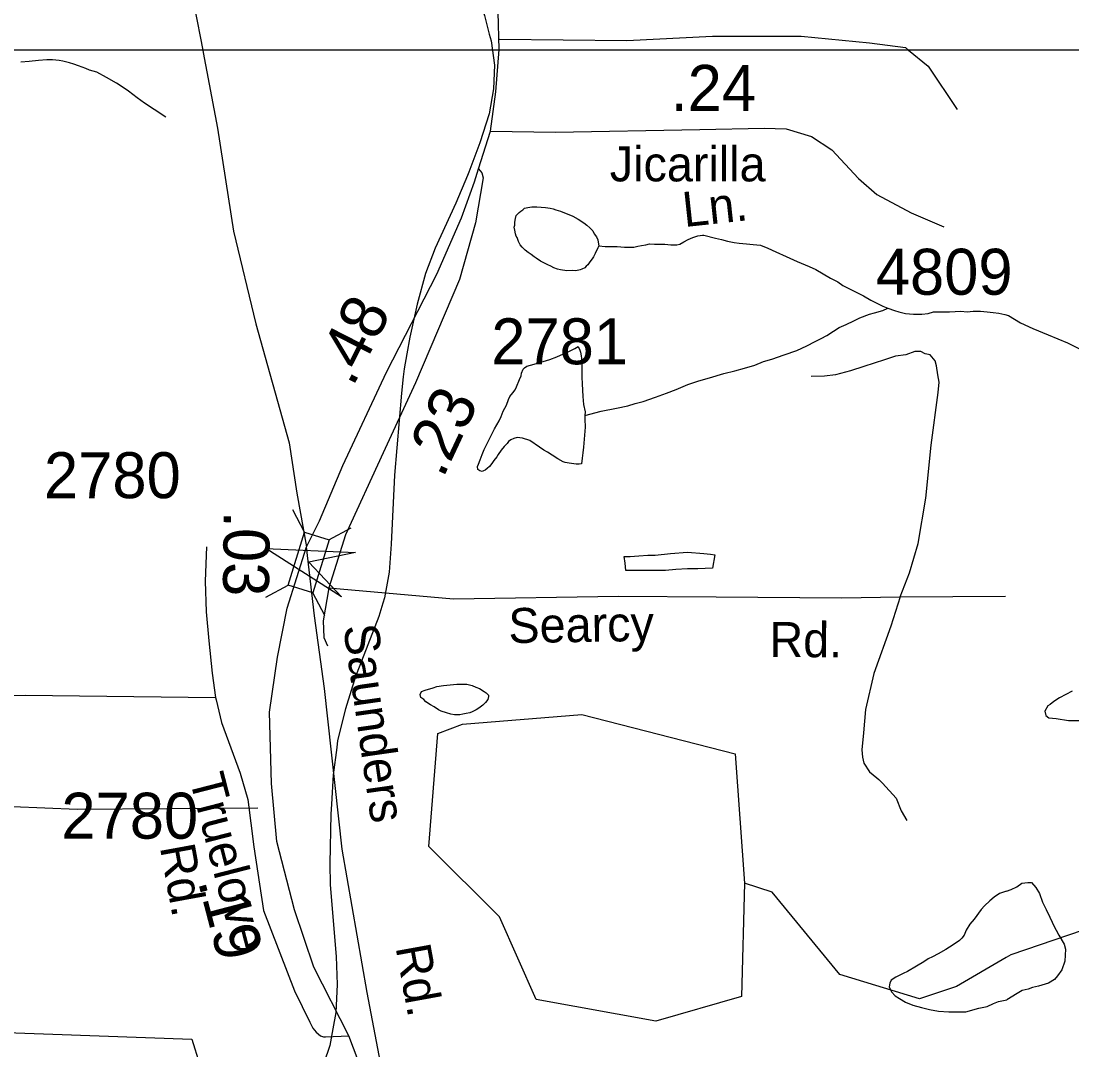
# Model space of a CAD drawing. Extents: x 2001466 to 2224147, y 644118 to 847247.
# Drawn here: x 2071761 to 2074618, y 655454 to 658253 of the extents above; entities that cross this region are included whole.
import ezdxf

# ---------------------------------------------------------------- set-up
doc = ezdxf.new("R2010")
doc.units = 0
for name, color, linetype in [('Exist Boundary Political City Limit New', 7, 'Continuous'), ('Exist Hydrographic Misc Water Feature', 7, 'Continuous'), ('Exist Railroad Mainline', 7, 'Continuous'), ('Exist Road Non-System Type 51', 7, 'Continuous'), ('Exist Road Non-System Type 51 Label', 7, 'Continuous'), ('Exist Road Primary NC Attributed', 7, 'Continuous'), ('Exist Road Primary NC Service Mileage Hundredths English Label', 7, 'Continuous'), ('Exist Road Primary NC Structure Standard Bridge CELL', 7, 'Continuous'), ('Exist Road Secondary Mileage Hundredths English Label', 7, 'Continuous'), ('Exist Road Secondary Structure Standard Bridge Attributed CELL', 7, 'Continuous'), ('Exist Road Secondary Type 51 Attributed', 7, 'Continuous'), ('Exist Road Secondary Type 51 Label', 7, 'Continuous'), ('Exist Road Secondary Type 51 Number Label', 7, 'Continuous'), ('Map Preparation Boundary City Limit Buffer Line', 7, 'Continuous'), ('Map Preparation Inset Cut Line', 7, 'Continuous')]:
    doc.layers.add(name, color=color, linetype=linetype)

msp = doc.modelspace()

# ---------------------------------------------------------------- linework, layer by layer
at = {"layer": 'Exist Boundary Political City Limit New'}
msp.add_lwpolyline([(2070007.4, 655563.6), (2072225.1, 655483.6), (2072246.1, 655416.9), (2072265, 655359.6), (2072449.4, 655349.1), (2072634.1, 655340.1), (2072657.8, 655272), (2072670, 655228.4), (2072685.6, 655160.9), (2072704.4, 655074.9), (2072724.5, 655000)], dxfattribs=at)
at = {"layer": 'Exist Hydrographic Misc Water Feature'}
for p, q in [((2072978.1, 657841.3), (2072974.9, 657832.8)), ((2072674.3, 656479.2), (2072670.8, 656469.9)), ((2072600.8, 655961.3), (2072601.9, 655903.3)), ((2074451.8, 655713), (2074439.1, 655705.7))]:
    msp.add_line(p, q, dxfattribs=at)
for points in [[(2073007, 658307.3), (2073020.8, 658267.5), (2073034.1, 658216.6)], [(2073007, 658307.3), (2073020.8, 658267.5), (2073034.1, 658216.6)], [(2073034.1, 658216.6), (2073038.8, 658198.8), (2073047.9, 658133.1)], [(2073034.1, 658216.6), (2073038.8, 658198.8), (2073047.9, 658133.1)], [(2072155.1, 657991.7), (2072123.1, 658011.7), (2072097, 658029.6), (2072076.9, 658043.6), (2072052.9, 658061.6), (2072033.1, 658075.5), (2072021, 658083.5), (2071993.1, 658099.4), (2071966.8, 658113.3), (2071946.9, 658119.3), (2071936.9, 658123.3), (2071917, 658131.2), (2071904.9, 658135.2), (2071892.8, 658139.2), (2071875, 658143.2), (2071864.9, 658145.2), (2071846.9, 658147.1), (2071830.9, 658147.1), (2071808.9, 658145.1), (2071782.9, 658143), (2071760.9, 658141)], [(2073047.9, 658133.1), (2073045.6, 658068.8), (2073033.7, 658000), (2073008.7, 657921.1), (2072978.1, 657841.3)], [(2073047.9, 658133.1), (2073045.6, 658068.8), (2073033.7, 658000), (2073008.7, 657921.1), (2072978.1, 657841.3)], [(2072974.9, 657832.8), (2072942.9, 657757.5), (2072886.7, 657635), (2072860.8, 657566), (2072837.9, 657482.6)], [(2072974.9, 657832.8), (2072942.9, 657757.5), (2072886.7, 657635), (2072860.8, 657566), (2072837.9, 657482.6)], [(2073331.6, 657641.8), (2073329.4, 657636.1), (2073321.6, 657620.2), (2073317.7, 657611.9), (2073313.6, 657606), (2073307.7, 657598), (2073301.7, 657589.9), (2073297.6, 657586.1), (2073293.5, 657581.9), (2073285.5, 657577.8), (2073281.4, 657576), (2073269.7, 657573.7), (2073259.9, 657574), (2073245.3, 657573.7), (2073227.5, 657576), (2073219.7, 657577.6), (2073209.8, 657582), (2073201.4, 657585.7), (2073193.6, 657589.7), (2073185.9, 657593.7), (2073173.6, 657599.6), (2073161.9, 657607.5), (2073155.7, 657611.7), (2073147.7, 657617.7), (2073139.7, 657623.4), (2073131.9, 657629.5), (2073123.5, 657637.7), (2073117.6, 657643.8), (2073113.3, 657653.4), (2073109.6, 657663.7), (2073107.5, 657667.6), (2073105.7, 657673.6), (2073103.4, 657683.6), (2073101.4, 657691.7), (2073103.2, 657697.5), (2073103.2, 657705.6), (2073105.5, 657715.4), (2073107.1, 657723.7), (2073111.2, 657727.5), (2073115.3, 657731.8), (2073119.4, 657735.6), (2073125.6, 657739.5), (2073129.7, 657743.8), (2073139.3, 657745.6), (2073149.4, 657747.7), (2073157.6, 657747.7), (2073163.5, 657747.6), (2073187.3, 657745.6), (2073199.4, 657743.8), (2073207.6, 657741.7), (2073215.2, 657739.7), (2073221.3, 657737.6), (2073227.3, 657735.9), (2073261.1, 657721.8), (2073275.7, 657713.9), (2073291.3, 657703.9), (2073299.2, 657697.8), (2073307.2, 657690.1), (2073315.2, 657682), (2073319.5, 657674.1), (2073325.3, 657665.9), (2073329.6, 657657.9), (2073331.4, 657645.9), (2073331.6, 657641.8)], [(2073331.6, 657641.8), (2073349.5, 657639.9), (2073365.3, 657639.9), (2073381.5, 657639.9), (2073401.6, 657638.1), (2073415.5, 657638), (2073427.4, 657638.2), (2073437.7, 657640.3), (2073447.7, 657642.1), (2073459.4, 657644.3), (2073469.6, 657646.4), (2073483.6, 657646.3), (2073497.7, 657646.2), (2073511.7, 657646.2), (2073527.5, 657644.5), (2073543.7, 657644.5), (2073551.7, 657646.2), (2073563.4, 657652.5), (2073575.2, 657658.4), (2073587.3, 657664.3), (2073595.3, 657666.7), (2073601.3, 657668.7), (2073613.4, 657670.5), (2073617.3, 657670.7)], [(2073617.3, 657670.7), (2073649.1, 657662.6), (2073665.1, 657658.6), (2073681.5, 657654.5), (2073699.5, 657650.5), (2073713.7, 657648.8), (2073733.1, 657646.6), (2073751.6, 657644.7), (2073771.3, 657642.9), (2073791.2, 657635), (2073813.3, 657624.8), (2073841.4, 657612.8), (2073871.5, 657598.9), (2073903.5, 657585.1), (2073921.4, 657577.2), (2073941.5, 657565.2), (2073961.6, 657553.2), (2073981.7, 657543.3), (2073995.2, 657533.1), (2074011.4, 657525.4), (2074031.9, 657515.4), (2074051.4, 657505.6), (2074071.5, 657493.6), (2074087.7, 657485.5), (2074103.7, 657477.4), (2074117.6, 657471.6)], [(2072837.9, 657482.6), (2072817.8, 657393.2), (2072809.8, 657347.9)], [(2072837.9, 657482.6), (2072817.8, 657393.2), (2072809.8, 657347.9)], [(2073294.1, 657180.2), (2073338.2, 657192.2), (2073380.2, 657200), (2073410.4, 657206.4), (2073430.5, 657212.3), (2073452.2, 657218.3), (2073486.1, 657230.2), (2073516.2, 657240.3), (2073542.2, 657250.5), (2073573.8, 657264.4), (2073604, 657274.4), (2073632.3, 657282.7), (2073672, 657294.6), (2073702, 657301), (2073727.8, 657308.8), (2073755.9, 657316.7), (2073779.7, 657326.9), (2073802, 657332.8), (2073835.9, 657345.2), (2073869.9, 657357), (2073897.8, 657369), (2073919.7, 657381.1), (2073935.9, 657389.2), (2073951.7, 657397.3), (2073970, 657409.2), (2073985.6, 657419.4), (2074004, 657427.2), (2074025.5, 657437.3), (2074041.7, 657445.4), (2074067.6, 657455.2), (2074081.5, 657459.6), (2074103.9, 657465.6), (2074117.6, 657471.6)], [(2074117.6, 657471.6), (2074135.7, 657465.6), (2074147.3, 657461.8), (2074165.4, 657457.8), (2074187.5, 657455.7), (2074209.7, 657455.6), (2074227.5, 657457.8), (2074241.7, 657461.7), (2074263.4, 657461.7), (2074285.5, 657461.9), (2074315.7, 657463.9), (2074333.5, 657462), (2074349.7, 657464), (2074369.6, 657463.8), (2074387.7, 657461.9), (2074403.9, 657459.8), (2074419.7, 657458.2), (2074435.6, 657454.2)], [(2074435.6, 657454.2), (2074445.9, 657452.2), (2074477.9, 657432.4), (2074511.7, 657416.7), (2074553.6, 657399), (2074605.6, 657377.8), (2074649.7, 657356.1), (2074691.8, 657346), (2074747.5, 657334.3), (2074799.6, 657330.5), (2074841.7, 657334.7), (2074877.3, 657350.7), (2074905.4, 657372.9), (2074933.1, 657397.1), (2074961, 657411.1), (2074981.1, 657417.4), (2074997.1, 657421)], [(2073294.1, 657180.2), (2073294.1, 657170.1), (2073294.3, 657148.1), (2073292.3, 657116), (2073290.4, 657094), (2073288.2, 657078.1), (2073286.7, 657064.1), (2073284.9, 657048.2), (2073278.5, 657048), (2073270.3, 657048), (2073250.9, 657050.1), (2073240.4, 657052.1), (2073234.9, 657053.8), (2073220.5, 657062), (2073204.7, 657071.7), (2073192.4, 657080.1), (2073182.8, 657086), (2073170.5, 657093.9), (2073144.6, 657111.6), (2073124.3, 657118), (2073110.2, 657119.7), (2073100.6, 657117.5), (2073092.8, 657113.9), (2073086.4, 657109.5), (2073082.5, 657103.6), (2073074.3, 657095.5), (2073066.7, 657085.7), (2073058.3, 657073.6), (2073054.8, 657067.7), (2073046.6, 657057.5), (2073040.7, 657049.5), (2073034.7, 657041.5), (2073028.6, 657035.5), (2073022.8, 657031.5), (2073018.7, 657029.7), (2073014.4, 657027.5), (2073008.5, 657029.7), (2073002.7, 657033.4), (2073002.3, 657041.5), (2073004.8, 657047.7), (2073008.9, 657059.6), (2073014.6, 657073.8), (2073020.6, 657087.5), (2073038.6, 657123.6), (2073048.3, 657143.7), (2073060.6, 657165.7), (2073066.3, 657177.5), (2073072.1, 657191.6), (2073080.7, 657207.7), (2073086.2, 657223.5), (2073090.3, 657231.8), (2073098.3, 657241.5), (2073104.2, 657249.6), (2073108.1, 657257.5), (2073116.1, 657277.8), (2073120.4, 657287.7), (2073122.1, 657295.5), (2073126.4, 657305.8), (2073130.1, 657309.7), (2073136.2, 657313.7), (2073156.3, 657319.6), (2073198.4, 657331.9), (2073217.8, 657339.8), (2073235.9, 657348.1), (2073250, 657354), (2073266.2, 657362.1), (2073276.1, 657367.9), (2073280, 657358), (2073282, 657352), (2073284.1, 657342), (2073286.1, 657327.9), (2073286.1, 657310), (2073286.1, 657295.8), (2073285.9, 657284.1), (2073286.3, 657266.2), (2073288.4, 657231.8), (2073290.2, 657210), (2073294.5, 657189.9), (2073294.1, 657180.2)], [(2072809.8, 657347.9), (2072802.8, 657307.3), (2072800.2, 657284.9)], [(2072809.8, 657347.9), (2072802.8, 657307.3), (2072800.2, 657284.9)], [(2072800.2, 657284.9), (2072795, 657240.5), (2072776.8, 657017.5), (2072766.9, 656830.5), (2072762, 656754.3), (2072748.9, 656683.8), (2072744.6, 656669.5)], [(2072800.2, 657284.9), (2072795, 657240.5), (2072776.8, 657017.5), (2072766.9, 656830.5), (2072762, 656754.3), (2072748.9, 656683.8), (2072744.6, 656669.5)], [(2073527.1, 656804.7), (2073573.2, 656808.6), (2073617.1, 656804.8), (2073635.1, 656802.9), (2073647, 656800.7), (2073641.1, 656764.7), (2073601.1, 656762.6), (2073573.2, 656762.8), (2073540.8, 656760.8), (2073512.9, 656758.5), (2073472.9, 656758.5), (2073457.1, 656758.4), (2073441.1, 656758.5), (2073417.2, 656758.4), (2073409.2, 656758.4), (2073404.9, 656758.3), (2073403.2, 656778.4), (2073401, 656796.2), (2073416.7, 656796.2), (2073440.9, 656798.2), (2073464.9, 656800.3), (2073485, 656800.5), (2073527.1, 656804.7)], [(2072744.6, 656669.5), (2072733.7, 656633.7), (2072674.3, 656479.2)], [(2072744.6, 656669.5), (2072733.7, 656633.7), (2072674.3, 656479.2)], [(2072670.8, 656469.9), (2072643.1, 656382.6), (2072621.8, 656296), (2072619.3, 656277.3)], [(2072670.8, 656469.9), (2072643.1, 656382.6), (2072621.8, 656296), (2072619.3, 656277.3)], [(2072959.9, 656449.7), (2072973.4, 656449.7), (2072987.6, 656445.5), (2072997.6, 656441.6), (2073007.7, 656437.6), (2073019.8, 656429.7), (2073025.9, 656425.5), (2073031.9, 656419.8), (2073032.1, 656415.7), (2073029.8, 656407.5), (2073023.9, 656399.9), (2073016.1, 656391.8), (2073005.8, 656383.6), (2072998, 656379.9), (2072988, 656373.7), (2072981.6, 656371.8), (2072971.6, 656369.7), (2072961.9, 656367.5), (2072953.9, 656365.5), (2072939.8, 656365.6), (2072930, 656367.5), (2072917.9, 656371.7), (2072903.7, 656375.5), (2072895.9, 656379.5), (2072884, 656387.4), (2072874, 656393.4), (2072861.7, 656401.3), (2072855.9, 656407.5), (2072847.9, 656413.5), (2072845.9, 656421.6), (2072849.8, 656429.5), (2072859.8, 656433.3), (2072881.6, 656439.3), (2072891.6, 656443.4), (2072909.9, 656445.5), (2072927.5, 656447.3), (2072945.7, 656449.4), (2072959.9, 656449.7)], [(2074618.6, 656430.4), (2074584.5, 656412), (2074568.5, 656402.3), (2074558.5, 656394.1), (2074552.3, 656390.1), (2074544.5, 656375.9), (2074546.8, 656364.2), (2074554.8, 656358.1), (2074574.9, 656356.3), (2074608.7, 656350.3), (2074642.8, 656350.5)], [(2073727.8, 655908.1), (2073719.8, 655599.9), (2073486.9, 655532.4), (2073161.9, 655591.5), (2073061.8, 655816.7), (2072869.9, 656007.6), (2072893.9, 656315.4), (2072960.9, 656340.4), (2073285.9, 656366.6), (2073702.8, 656259.7), (2073727.8, 655908.1)], [(2072619.3, 656277.3), (2072609.7, 656202.7), (2072604.7, 656122.8)], [(2072619.3, 656277.3), (2072609.7, 656202.7), (2072604.7, 656122.8)], [(2072604.7, 656122.8), (2072602.9, 656096.2), (2072600.8, 655961.3)], [(2072604.7, 656122.8), (2072602.9, 656096.2), (2072600.8, 655961.3)], [(2072601.9, 655903.3), (2072617.9, 655708.9), (2072620.7, 655632.2)], [(2072601.9, 655903.3), (2072617.9, 655708.9), (2072620.7, 655632.2)], [(2074439.1, 655705.7), (2074303.8, 655627.4), (2074203.7, 655593.3), (2073986.8, 655660.1), (2073802.9, 655883.6), (2073727.8, 655908.1)], [(2074440.4, 655886.3), (2074452.5, 655890.6), (2074468.3, 655898.3), (2074482.2, 655908.4), (2074498.2, 655910), (2074508, 655910.1), (2074520.1, 655896.1), (2074529.8, 655880.1), (2074538.2, 655856.1), (2074548, 655836.3), (2074558.3, 655816.1), (2074564, 655802.3)], [(2074440.4, 655886.3), (2074420.7, 655880.4), (2074406.7, 655870.3), (2074394.8, 655860.4), (2074380.5, 655846.3), (2074370.9, 655836.4), (2074352.4, 655810.4), (2074340.7, 655796.3), (2074330.9, 655780.4), (2074324.7, 655766.4), (2074318.8, 655758.4), (2074312.6, 655752.4), (2074294.8, 655740.1), (2074274.9, 655728.1), (2074254.8, 655716.1), (2074238.8, 655708), (2074226.9, 655702.1), (2074215, 655694.2), (2074195.1, 655682.2), (2074170.9, 655668), (2074159, 655662.1), (2074139.1, 655652.1), (2074126.6, 655643.9), (2074122.7, 655635.9), (2074121.1, 655626), (2074124.8, 655618.2)], [(2075676.8, 655625.8), (2075125.9, 655807.6), (2074842.9, 655846.1), (2074451.8, 655713)], [(2074564, 655802.3), (2074568.3, 655794.3), (2074582.3, 655766.3), (2074596.6, 655742.2), (2074600.5, 655728.2), (2074598.7, 655696.4), (2074590.9, 655672.5), (2074578.8, 655656.4), (2074570.8, 655646.3), (2074554.6, 655636.2), (2074526.9, 655628.2), (2074510.9, 655624.2), (2074498.8, 655620.3), (2074482.8, 655616.3), (2074468.9, 655608.3), (2074440.8, 655590.6)], [(2072620.7, 655632.2), (2072616.8, 655556.4), (2072608.8, 655512)], [(2072620.7, 655632.2), (2072616.8, 655556.4), (2072608.8, 655512)], [(2074124.8, 655618.2), (2074127.2, 655612.2), (2074137.1, 655602.1), (2074149, 655594.3), (2074165.2, 655584.1), (2074185.1, 655576.2), (2074209.1, 655570.1), (2074231, 655564.4), (2074255, 655560.3), (2074283.1, 655558.1), (2074307.1, 655558.1), (2074329.2, 655558.4), (2074365.3, 655568.4), (2074387.3, 655572.3), (2074405.1, 655580.6), (2074418.8, 655586.6), (2074440.8, 655590.6)], [(2072608.8, 655512), (2072601, 655467), (2072584.2, 655418.8)], [(2072608.8, 655512), (2072601, 655467), (2072584.2, 655418.8)]]:
    msp.add_lwpolyline(points, dxfattribs=at)
at = {"layer": 'Exist Railroad Mainline'}
for points in [[(2072232.7, 658289.3), (2072255.3, 658173.9), (2072256.6, 658167.2), (2072294.8, 657961.2), (2072338.9, 657681.1), (2072399.5, 657429.6), (2072490.4, 657105.5), (2072511, 656969.1), (2072537.3, 656822.6)], [(2074447.8, 652429.1), (2074089.7, 652777), (2073899.5, 652963), (2073767.5, 653112.9), (2073659.5, 653228.9), (2073509.3, 653406.7), (2073363.3, 653574.7), (2073255.2, 653712.7), (2073133.1, 653886.6), (2073043, 654076.6), (2072967, 654272.8), (2072914.7, 654476.6), (2072848.5, 654812.8), (2072811.5, 655023.4), (2072778.4, 655210.8), (2072702.2, 655610.9), (2072633.9, 656000.9), (2072585.7, 656437.2), (2072559.3, 656635.2), (2072537.3, 656822.6)]]:
    msp.add_lwpolyline(points, dxfattribs=at)
at = {"layer": 'Exist Road Non-System Type 51'}
msp.add_line((2074151.3, 656686.9), (2074437.3, 656688.9), dxfattribs=at)
for points in [[(2073062.3, 658203.6), (2073408.4, 658200), (2073641.2, 658211.3), (2073882.4, 658211.3), (2074067.5, 658193), (2074165.7, 658180.4), (2074173.7, 658173.9)], [(2074173.7, 658173.9), (2074227.4, 658129.9), (2074306, 658012)], [(2074151.3, 656686.9), (2074176.6, 656752.4), (2074200.3, 656831.9), (2074220.8, 656955.5), (2074235.7, 657099.2), (2074254.6, 657242.8), (2074257.2, 657270.8), (2074253.6, 657290.8), (2074250.1, 657314.9), (2074246.4, 657329), (2074232.7, 657345.3), (2074218.7, 657347.6), (2074206.9, 657353.8), (2074190.9, 657354.1), (2074166.7, 657344.6), (2074138.6, 657341.2), (2074108.4, 657331.8), (2074052, 657312.9), (2074015.8, 657301.7), (2073975.6, 657290.5), (2073945.5, 657287.1), (2073909.5, 657285.8)], [(2072597.7, 656711.1), (2072582.1, 656621.5), (2072583.9, 656575.8), (2072594.3, 656553.2)], [(2072597.7, 656711.1), (2072937.2, 656681.6), (2073385.3, 656688.5), (2073651.3, 656687.1), (2073991.2, 656684.2), (2074151.3, 656686.9)], [(2074151.3, 656686.9), (2074125.7, 656607.4), (2074079.1, 656478.4), (2074057.1, 656380.8), (2074051.8, 656316.9), (2074046.8, 656271), (2074048.4, 656251), (2074052.1, 656234.9), (2074067.6, 656210.6), (2074087.3, 656194.2), (2074093.2, 656190.1), (2074103, 656179.9), (2074140.1, 656139.1), (2074153.5, 656104.9), (2074168.9, 656078.6)], [(2072405.3, 656112), (2071913.5, 656108.4), (2071737.7, 656115.9), (2071693.6, 656112.8), (2071667.5, 656109.3), (2071645.5, 656107.8), (2071633.3, 656098), (2071609, 656084.5), (2071592.6, 656064.9), (2071578.2, 656043.2), (2071569.6, 656015.3), (2071559, 655985.5)]]:
    msp.add_lwpolyline(points, dxfattribs=at)
at = {"layer": 'Exist Road Primary NC Attributed'}
for points in [[(2073037.2, 657953), (2073051.8, 658059.8), (2073061.3, 658175), (2073058.6, 658276.6), (2073052.4, 658401.2), (2073044.5, 658524.8), (2073028.8, 658684), (2073014.2, 658871.5)], [(2073005, 657851.2), (2073037.2, 657953)], [(2072537.3, 656822.6), (2072572.1, 656893.9), (2072636.1, 657043.8), (2072754.9, 657298), (2072891.2, 657564.5), (2072958.2, 657717.4), (2072993.8, 657815.8), (2073005, 657851.2)], [(2072652.1, 655493), (2072557.4, 655679.9), (2072504.4, 655835.3), (2072456.9, 656021.8), (2072442.3, 656179), (2072436.8, 656372.8), (2072458.7, 656522.7), (2072484.3, 656656.2), (2072537.3, 656822.6)], [(2073243.5, 653687.9), (2073085.9, 653900.1), (2073002.7, 654036.3), (2072949.3, 654163), (2072905.3, 654306.5), (2072862.9, 654505.4), (2072821.6, 654799.7), (2072790.2, 655036.4), (2072748.4, 655193.5), (2072710.7, 655340.1), (2072652.1, 655493)]]:
    msp.add_lwpolyline(points, dxfattribs=at)
at = {"layer": 'Exist Road Primary NC Structure Standard Bridge CELL'}
for p, q in [((2072532.1, 656862.5), (2072499.9, 656923.5)), ((2072598, 656842.1), (2072659, 656874.4)), ((2072426.2, 656685.9), (2072487.2, 656718.2)), ((2072586.9, 656636.4), (2072554.7, 656697.4))]:
    msp.add_line(p, q, dxfattribs=at)
msp.add_lwpolyline([(2072487.2, 656718.2), (2072531.8, 656862.6), (2072599.2, 656841.8), (2072554.7, 656697.4)], close=True, dxfattribs=at)
at = {"layer": 'Exist Road Secondary Structure Standard Bridge Attributed CELL'}
msp.add_lwpolyline([(2072632.3, 656686.8), (2072427, 656818.5), (2072670.6, 656807.1), (2072543.2, 656781.5)], close=True, dxfattribs=at)
at = {"layer": 'Exist Road Secondary Type 51 Attributed'}
for points in [[(2073037.2, 657953), (2073213.9, 657950.1), (2073606.6, 657957.5), (2073781.3, 657961.8), (2073841.4, 657959.6), (2073910, 657938.5), (2073964.9, 657902.6), (2074037.7, 657824.4), (2074087.4, 657781.1), (2074181.3, 657731.5), (2074270, 657693.5)], [(2073005, 657851.2), (2073013.7, 657839.6), (2073017.3, 657826.5), (2072997, 657704), (2072952.7, 657549.8), (2072833.5, 657268.7), (2072745.8, 657078.6), (2072643.4, 656855.5), (2072597.7, 656711.1)], [(2072265.5, 656823.2), (2072261.7, 656729.4), (2072264.2, 656645.6), (2072271.3, 656567), (2072280.7, 656479.6), (2072290, 656413.5)], [(2070807.9, 656622.8), (2071067.2, 656582.7), (2071192.8, 656550.6), (2071297.1, 656499.7), (2071398.6, 656451.6), (2071502.9, 656424.9), (2071588.4, 656416.8), (2071772.8, 656419.5), (2072290, 656413.5)], [(2072290, 656413.5), (2072291.9, 656406.7), (2072306.1, 656344.7), (2072356.5, 656207.7), (2072378, 656135.9), (2072394.2, 656006.8), (2072420.2, 655833.7), (2072505, 655615.1), (2072546.3, 655530.2), (2072554.5, 655514.2), (2072563.4, 655503.2), (2072575, 655493.2), (2072583.5, 655490), (2072588.5, 655490.1), (2072652.1, 655493)]]:
    msp.add_lwpolyline(points, dxfattribs=at)
at = {"layer": 'Map Preparation Boundary City Limit Buffer Line'}
msp.add_lwpolyline([(2070007.4, 655563.6), (2072225.1, 655483.6), (2072246.1, 655416.9), (2072265, 655359.6), (2072449.4, 655349.1), (2072634.1, 655340.1), (2072657.8, 655272), (2072670, 655228.4), (2072685.6, 655160.9), (2072704.4, 655074.9), (2072724.5, 655000)], dxfattribs=at)
at = {"layer": 'Map Preparation Inset Cut Line'}
for p, q in [((2072255.3, 658173.9), (2070058.4, 658173.9)), ((2073022.2, 658173.9), (2072255.3, 658173.9)), ((2074173.7, 658173.9), (2073022.2, 658173.9)), ((2074710.2, 658173.9), (2074173.7, 658173.9))]:
    msp.add_line(p, q, dxfattribs=at)

# ---------------------------------------------------------------- texts
at = {"layer": 'Exist Road Non-System Type 51 Label'}
for s, rotation, p in [('Searcy', 0.8825, (2073086.8, 656560.9)), ('Rd.', 359.5112, (2073795.4, 656523.7)), ('Saunders', 278.1441, (2072636.7, 656606.3)), ('Rd.', 280.3544, (2072779, 655734.1))]:
    msp.add_text(s, height=95, rotation=rotation, dxfattribs=at).set_placement(p)
at = {"layer": 'Exist Road Primary NC Service Mileage Hundredths English Label'}
msp.add_text('.48', height=125, rotation=62.914, dxfattribs=at).set_placement((2072662.9, 657255.2))
at = {"layer": 'Exist Road Secondary Mileage Hundredths English Label'}
for s, rotation, p in [('.24', 359.99, (2073526.9, 658008.4)), ('.23', 64.9577, (2072908, 657006.6)), ('.03', 269.3782, (2072312.4, 656921.1)), ('.19', 284.647, (2072241.4, 655913.7))]:
    msp.add_text(s, height=125, rotation=rotation, dxfattribs=at).set_placement(p)
at = {"layer": 'Exist Road Secondary Type 51 Label'}
msp.add_text('Jicarilla', height=95, dxfattribs=at).set_placement((2073361.6, 657816.7))
for s, rotation, p in [('Ln.', 6.145, (2073564.5, 657692.3)), ('Truelove', 284.4292, (2072218.1, 656194)), ('Rd.', 280.3535, (2072138.3, 656006.4))]:
    msp.add_text(s, height=95, rotation=rotation, dxfattribs=at).set_placement(p)
at = {"layer": 'Exist Road Secondary Type 51 Number Label'}
for s, p in [('4809', (2074084.8, 657508.4)), ('2781', (2073039.5, 657319.2)), ('2780', (2071823.5, 656955.1)), ('2780', (2071870.8, 656029.1))]:
    msp.add_text(s, height=125, dxfattribs=at).set_placement(p)

doc.saveas('drawing.dxf')
